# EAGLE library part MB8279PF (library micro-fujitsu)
MICROCONTROLLER/MEMORY DEVICE
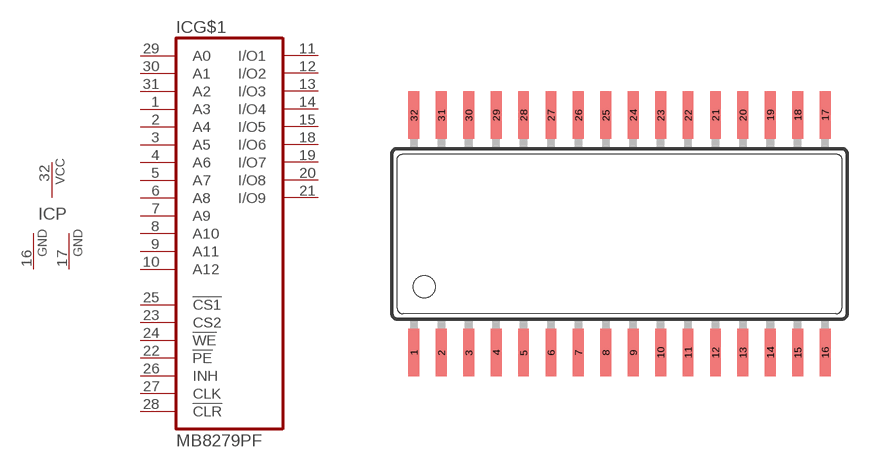
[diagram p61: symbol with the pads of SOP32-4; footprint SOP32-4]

Designator prefix IC; gates G$1=MB8279RT P=VCC-GNDQ

## MB8279PF (OC_FARNELL: unknown; OC_NEWARK: unknown)  [SOP32-4]
1  G$1:A3  in
2  G$1:A4  in
3  G$1:A5  in
4  G$1:A6  in
5  G$1:A7  in
6  G$1:A8  in
7  G$1:A9  in
8  G$1:A10  in
9  G$1:A11  in
10  G$1:A12  in
11  G$1:I/O1
12  G$1:I/O2
13  G$1:I/O3
14  G$1:I/O4  nc
15  G$1:I/O5
16  P:GND  pwr
17  P:GNDQ  pwr
18  G$1:I/O6
19  G$1:I/O7
20  G$1:I/O8
21  G$1:I/O9
22  G$1:!PE  in
23  G$1:CS2  in
24  G$1:!WE  in
25  G$1:!CS1  in
26  G$1:INH  in
27  G$1:CLK  in
28  G$1:!CLR  in
29  G$1:A0  in
30  G$1:A1  in
31  G$1:A2  in
32  P:VCC  pwr

## Footprint SOP32-4 (pad centres in mm)
Small Outline Package
smd 0.5 x 2.2: 1 -9.525,-5.5; 2 -8.255,-5.5; 3 -6.985,-5.5; 4 -5.715,-5.5; 5 -4.445,-5.5; 6 -3.175,-5.5; 7 -1.905,-5.5; 8 -0.635,-5.5; 9 0.635,-5.5; 10 1.905,-5.5; 11 3.175,-5.5; 12 4.445,-5.5; 13 5.715,-5.5; 14 6.985,-5.5; 15 8.255,-5.5; 16 9.525,-5.5; 17 9.525,5.5; 18 8.255,5.5; 19 6.985,5.5; 20 5.715,5.5; 21 4.445,5.5; 22 3.175,5.5; 23 1.905,5.5; 24 0.635,5.5; 25 -0.635,5.5; 26 -1.905,5.5; 27 -3.175,5.5; 28 -4.445,5.5; 29 -5.715,5.5; 30 -6.985,5.5; 31 -8.255,5.5; 32 -9.525,5.5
